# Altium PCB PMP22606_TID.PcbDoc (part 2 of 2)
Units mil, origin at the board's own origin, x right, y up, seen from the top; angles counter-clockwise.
Board outline 6300 x 4500 mil, 2 copper layers (Top Layer, Bottom Layer), stack 62 mil thick; 94 components, 37 nets, 207 pads, 120 vias.
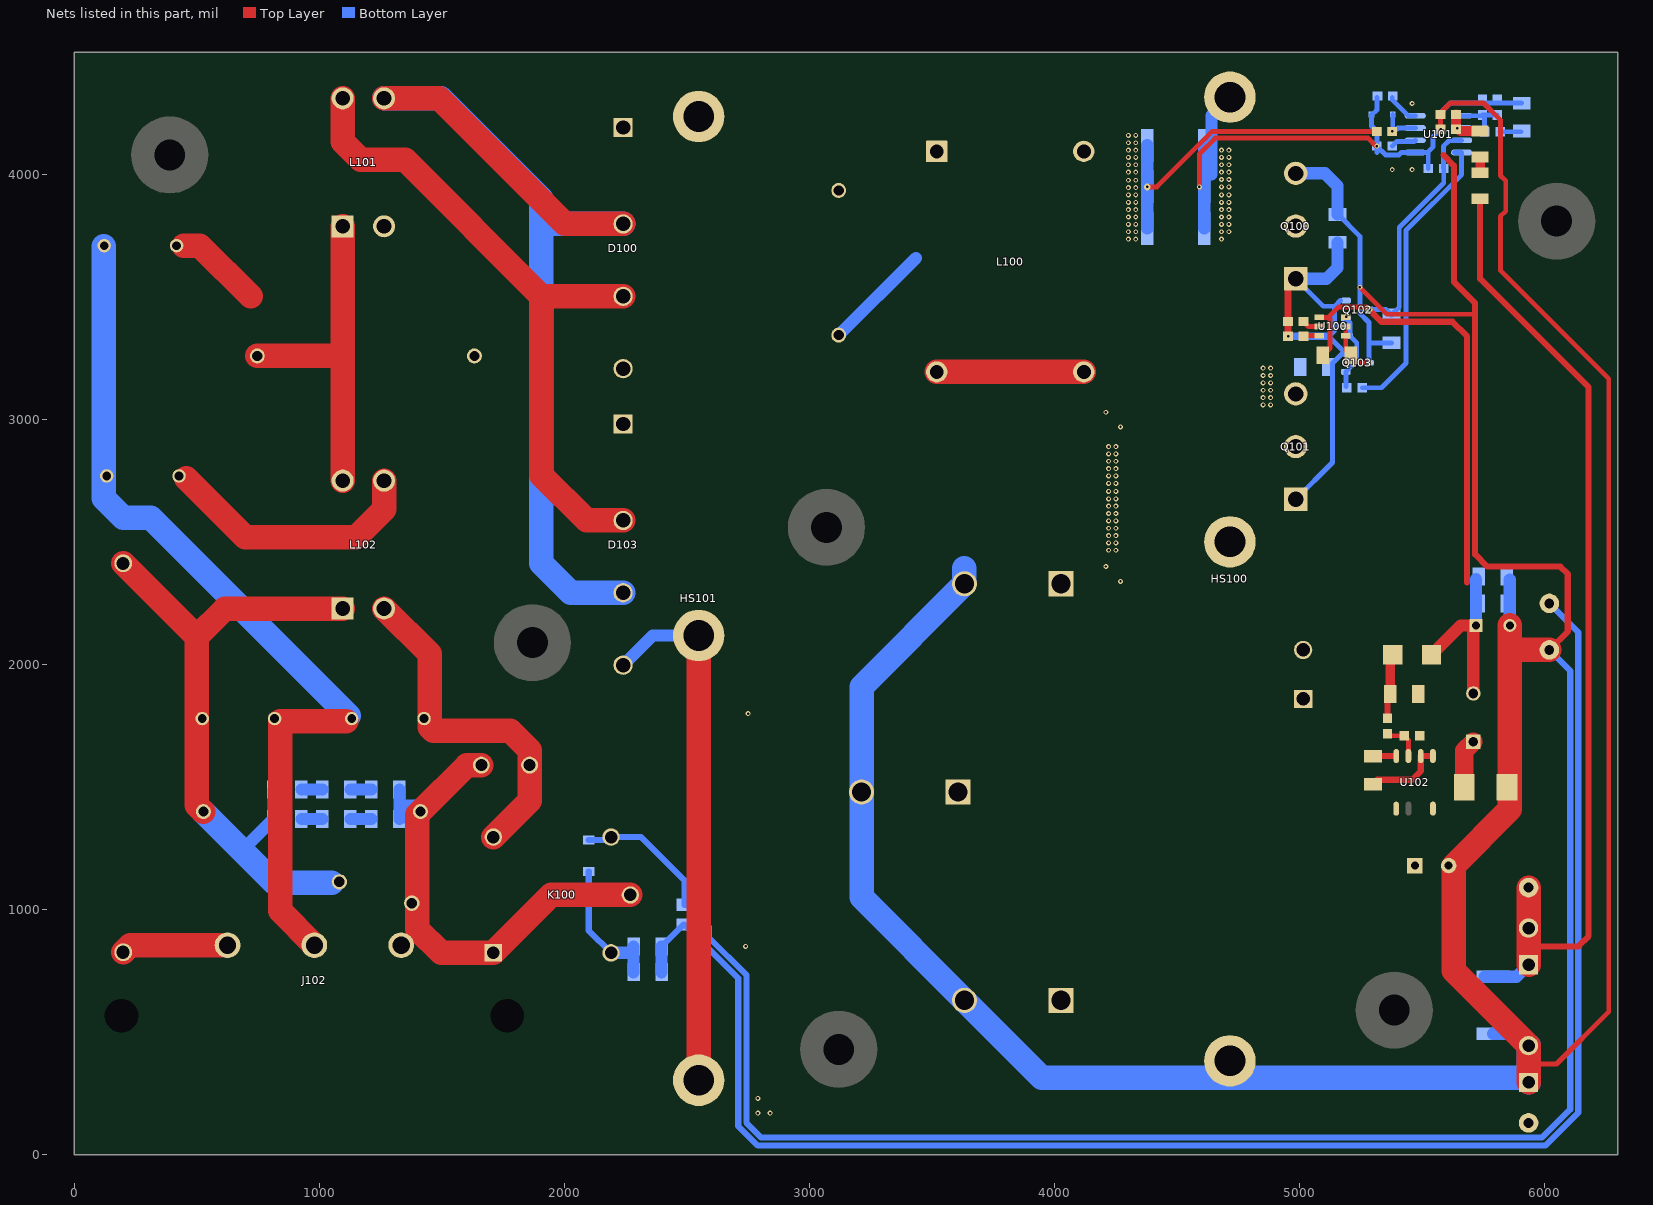
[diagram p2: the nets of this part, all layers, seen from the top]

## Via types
v1: diameter 20, hole 10, Top Layer to Bottom Layer, 112 vias
v2: diameter 28, hole 10, Top Layer to Bottom Layer, 8 vias

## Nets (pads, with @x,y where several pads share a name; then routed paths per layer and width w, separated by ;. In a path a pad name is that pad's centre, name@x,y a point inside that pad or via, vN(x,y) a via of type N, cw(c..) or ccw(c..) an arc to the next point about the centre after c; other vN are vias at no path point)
15V: 15V.1 C110.1 C111.1 C112.1 C113.2 C123.1 D107.2 L103.2 Q102.3 R118.2 R120.2 R126.2 R127.2 U100.1 U101.7 | length 10284.2
  Top Layer w20: U100.1@5081.06,3417.4 5117.8,3417.4 ; C111.1@5095.79,3262.49 5125.2,3291.89 5125.2,3410 5117.8,3417.4 ; v2(5284.96,3449.06) 5274.02,3460 5160.39,3460 5117.8,3417.4
  Top Layer w25: v2(5284.96,3449.06) 5334.39,3399.63 5624.59,3399.63 5684.53,3339.68 5684.53,2336.5
  Top Layer w50: D107.2@5538.74,2040 5658.74,2160 C123.1@5721.1,2160 ; L103.2@5710,1882.43 C123.1@5710,2148.9
  Bottom Layer w20: Q102.3@5284.57,3449.06 5353.23,3449.06 C110.1@5375.2,3427.09 5407.32,3459.21 5407.32,3784.1 5589.02,3965.8 C112.1@5589.02,4024.88 ; C112.1@5587.52,4026.38 5587.52,4114.88 5612.52,4139.88 U101.7@5662.01,4139.88
  Bottom Layer w25: R120.2@2397.09,850 2487.09,940 C113.2@2490,940 2710,720 2710,117.13 2790,37.13 6003.62,37.13 6138.07,171.58 6138.07,2131.93 15V.1@6020,2250
  Bottom Layer w50: R118.2@2397.09,745.04 R120.2@2397.09,850 ; C123.1@5721.1,2160 R126.2@5721.1,2348.5
B+: C101.1 C102.1 C103.1 C122.1 D101.1 J100.1 J100.2 R100.2 R117.2 U102.5 U102.8 Vout.1 | length 4119.7
  Top Layer w25: R117.2@5737.52,3901.73 5737.52,3575 6180,3132.52 6180,891.93 6138.07,850 5935.2,850
  Top Layer w100: J100.1@5935.2,775 5935.2,850 J100.2@5935.2,925 Vout.1@5935.2,1090
  Bottom Layer w50: R100.2@5756.02,726.14 5886.34,726.14 J100.1@5935.2,775 J100.2@5935.2,925
GND: C101.2 C102.2 C103.2 C110.2 C111.2 C112.2 C113.1 C114.2 C115.2 C116.2 C117.2 C118.2 C119.2 C122.2 C123.2 D104.1 D106.2 D108.2 GND.1 HS100.1 HS100.2 HS100.3 J101.1 J101.2 K100.5 Q100.3 Q101.3 Q103.3 R100.1 R101.1 R102.1 R105.2 R106.2 R109.2 R122.1 R123.1 R126.1 R127.1 U100.4 U100.5 U101.1 | length 25603.5
  Top Layer w20: v1(4592.17,3950) 4592.17,4084.52 4656.11,4148.46 5280.23,4148.46 5312.69,4116 v1(5316.02,4116) ; U100.5@5189.33,3380 U100.4@5189.33,3342.6 5189.33,3283.12 C111.2@5209.96,3262.49 5240.28,3232.17 v2(5284.1,3232.17) ; v1(5247.01,3540) 5357.01,3430 5717.4,3430 ; v2(5576.02,4184.88) C118.2@5576.02,4244.88 ; C118.2@5576.02,4251.81 5616.18,4291.97 5751.26,4291.97 5820.02,4223.21 5820.02,3996.28 5841.97,3974.33 5841.97,3851.08 5820.02,3829.14 5820.02,3609.17 6262.5,3166.69 6262.5,583.13 6049.37,370 5935.2,370
  Top Layer w25: 5587.52,4080 5630.57,4036.95 5630.57,3561.74 5717.4,3474.91 5717.4,3430 5717.4,2450 5767.4,2400 6065,2400 6095,2370 6095,2135 GND.1@6020,2060
  Top Layer w100: C123.2@5858.9,2160 5858.9,1408.9 5630,1180 5630,750.2 J101.2@5935.2,445 5935.2,370 J101.1@5935.2,295 ; 5878.9,2060 GND.1@6020,2060
  Bottom Layer w20: R101.1@5158.11,3837.09 5247.01,3748.19 v1(5247.01,3540) 5247.01,3433.3 5284.1,3396.21 v2(5284.1,3232.17) ; D106.2@5294.21,4244.88 5294.21,4198.15 C114.2@5316.02,4176.34 C115.2@5316.02,4116.34 v1(5316.02,4116) C115.2@5316.02,4115.67 ; 5298.11,3312.91 C110.2@5375.2,3312.91 ; 5307.52,4254.88 5316.02,4263.39 R122.1@5316.02,4314.88 ; 5316.02,4089.38 C115.2@5316.02,4115.67 ; C112.2@5526.02,4024.88 5526.02,4093.39 ; C119.2@5907.52,4291.97 5616.18,4291.97 5576.02,4251.81 v2(5576.02,4184.88) 5546.02,4154.88 5546.02,4113.39 5526.02,4093.39 ; C115.2@5316.02,4115.67 5351.93,4079.76 5406.1,4079.76 5416.22,4089.88 U101.1@5473.03,4089.88 5522.52,4089.88 5526.02,4093.39
  Bottom Layer w25: D104.1@2100,1284.47 K100.5@2179.04,1284.47 ; K100.5@2190.79,1296.22 2313.78,1296.22 2490,1120 C113.1@2490,1020 2500,1020 2590,930 2590,886.49 2742.87,733.62 2742.87,130.74 2803.62,70 5990,70 6105.2,185.2 6105.2,1974.8 GND.1@6020,2060
  Bottom Layer w50: R109.2@4611.34,3780 R106.2@4611.34,3950 R105.2@4611.34,4120 ; 4641.34,4000 4641.34,4240.91 HS100.1@4716.54,4316.1 ; Q100.3@4985.2,4005 5104.2,4005 5155.2,3954.01 R101.1@5155.2,3837.09 ; R100.1@5790,493.86 5886.34,493.86 J101.2@5935.2,445 ; C123.2@5858.9,2160 R126.1@5858.9,2347.87
  Bottom Layer w100: 3633.15,2392.95 C101.2@3633.15,2330 3213.15,1910 C102.2@3213.15,1480 3213.15,1050 C103.2@3633.15,630 3948.43,314.72 J101.1@5915.47,314.72 ; J101.1@5935.2,295 J101.2@5935.2,445
  other v1: 2790,170 2840,170 2790,230 2740,850 2750,1800 4270,2340 4210,2400.62 4221.34,2466.77 4251.34,2466.77 4221.34,2496.77 4251.34,2496.77 4221.34,2526.77 4251.34,2526.77 4221.34,2556.77 4251.34,2556.77 4221.34,2586.77 4251.34,2586.77 4221.34,2616.77 4251.34,2616.77 4221.34,2646.77 4251.34,2646.77 4221.34,2676.77 4251.34,2676.77 4221.34,2706.77 4251.34,2706.77 4221.34,2740 4251.34,2740 4221.34,2770 4251.34,2770 4221.34,2800 4251.34,2800 4221.34,2830 4251.34,2830 4221.34,2860 4251.34,2860 4221.34,2890 4251.34,2890 4270,2970 4210,3030 4852.2,3060 4882.2,3060 4852.2,3090 4882.2,3090 4852.2,3120 4882.2,3120 4852.2,3150 4882.2,3150 4852.2,3180 4882.2,3180 4852.2,3210 4882.2,3210 4682.2,3736.77 4682.2,3766.77 4712.2,3766.77 4682.2,3796.77 4712.2,3796.77 4682.2,3826.77 4712.2,3826.77 4682.2,3856.77 4712.2,3856.77 4682.2,3886.77 4712.2,3886.77 4682.2,3916.77 4712.2,3916.77 4682.2,3950 4712.2,3950 4682.2,3980 4712.2,3980 4682.2,4010 4712.2,4010 5379.02,4020 5460,4020 4682.2,4040 4712.2,4040 4682.2,4070 4712.2,4070 4682.2,4100 4712.2,4100 5460,4290
NetC100_1: C100.1 D100.1 D103.1 L100.1 L100.2
NetC100_2: C100.2 D100.4 D103.4 HS101.1 HS101.2 HS101.3 R105.1 R106.1 R109.1 R115.2 | length 3990.3
  Top Layer w20: v2(4379.06,3950) 4418.23,3950 4618.23,4150 4644.57,4176.34 R115.2@5316.02,4176.34
  Top Layer w100: HS101.1@2548.66,303.9 HS101.2@2548.66,2118.86
  Bottom Layer w50: D103.4@2240,1997.87 2360.98,2118.86 HS101.2@2548.66,2118.86 ; C100.2@3120,3344.72 3435.28,3660 ; R109.1@4379.06,3780 v2(4379.06,3950) R105.1@4379.06,4120
  other v1: 4302.2,3736.77 4332.2,3736.77 4302.2,3766.77 4332.2,3766.77 4302.2,3796.77 4332.2,3796.77 4302.2,3826.77 4332.2,3826.77 4302.2,3856.77 4332.2,3856.77 4302.2,3886.77 4332.2,3886.77 4302.2,3916.77 4332.2,3916.77 4302.2,3946.77 4332.2,3946.77 4302.2,3976.77 4332.2,3976.77 4302.2,4010 4332.2,4010 4302.2,4040 4332.2,4040 4302.2,4070 4332.2,4070 4302.2,4100 4332.2,4100 4302.2,4130 4332.2,4130 4302.2,4160 4332.2,4160
NetC104_1: C104.1 C106.1 F100.2 L102.1 R103.2 R104.2 RV100.2 | length 2720.5
  Top Layer w100: F100.2@200,2413.7 500,2113.7 ; C106.1@527.09,1400 500,1427.09 500,2113.7 ; L102.1@1095.5,2229 615.3,2229 500,2113.7
  Bottom Layer w50: 696.46,1253.54 R103.2@812.91,1370 R104.2@812.91,1490
  Bottom Layer w100: C106.1@527.09,1400 817.09,1110 1050.31,1110
NetC105_1: C105.1 C107.1 L101.1 L102.4 | length 1735.3
  Top Layer w100: 446.81,3710 513.15,3710 720,3503.15 ; C107.1@747.09,3260 1085.5,3260 ; L102.4@1095.5,2751 L101.1@1095.5,3789
NetC106_2: C106.2 J102.2 K100.1 K100.3 R110.1 R111.1 R112.2 RV100.1 | length 1992.5
  Top Layer w100: R112.2@1661.57,1590 1602.91,1590 C106.2@1412.91,1400 1400,1387.09 1400,920.67 1496.89,823.78 K100.1@1710.47,823.78 1946.69,1060 K100.3@2269.53,1060
  Bottom Layer w50: R110.1@1327.09,1370 R111.1@1327.09,1490
  Bottom Layer w100: 1359.92,1400 C106.2@1412.91,1400
NetC107_2: C107.2 C109.2 L101.2 L102.3 | length 1070.7
  Top Layer w100: 457.17,2760 697.17,2520 1150,2520 1264.5,2634.5 L102.3@1264.5,2751
NetC108_2: C108.2 K100.2 L102.2 R112.1 | length 1424.6
  Top Layer w100: L102.2@1264.5,2229 1450,2043.5 1450,1744.99 1464.99,1730 1780,1730 1858.43,1651.57 R112.1@1858.43,1590 1858.43,1444.17 K100.2@1710.47,1296.22
NetC114_1: C114.1 D106.1 R115.1 U101.3 | length 166.4
  Bottom Layer w20: v2(5379.02,4176.34) 5388.98,4176.34 5402.52,4189.88 U101.3@5473.03,4189.88 ; C114.1@5380.83,4178.15 D106.1@5380.83,4244.88
NetC115_1: C115.1 U101.2 | length 103.8
  Bottom Layer w20: C115.1@5379.02,4116.34 5397.56,4134.88 5468.03,4134.88 U101.2@5473.03,4139.88
NetC116_1: C116.1 C117.1 R121.2 U101.5 | length 219
  Bottom Layer w20: U101.5@5662.01,4239.88 5744.02,4239.88 C117.1@5747.52,4243.39 ; R121.2@5756.02,4174.88 5756.02,4234.88 C117.1@5747.52,4243.39 ; C116.1@5807.52,4243.39 C117.1@5747.52,4243.39
NetC118_1: C118.1 R119.1 R123.2 U101.6 | length 155.4
  Top Layer w39.37: C118.1@5639.02,4244.88 5639.02,4195.08 v2(5644.21,4189.88) 5656.06,4178.03 R119.1@5737.52,4178.03
NetC119_1: C119.1 R121.1 | length 85.6
  Bottom Layer w20: R121.1@5819.02,4174.88 C119.1@5904.61,4174.88
NetC120_1: C120.1 D107.1 R124.2 | length 237.2
  Top Layer w25: R124.2@5360,1781.5 C120.1@5360,1868.58
  Top Layer w39.37: C120.1@5371.42,1880 D107.1@5371.42,2030.16
NetC120_2: C120.2 C121.2 D108.1 L103.1 R125.1 U102.1 U102.2 | length 529.4
  Top Layer w25: C121.2@5300,1512.47 5317.53,1530 5459.69,1530 5495,1565.32 U102.2@5495,1627.02 U102.1@5545,1627.02
  Top Layer w75: D108.1@5672.99,1500.05 5672.99,1648.57 L103.1@5710,1685.57
NetC121_1: C121.1 U102.4 | length 94.6
  Top Layer w25: C121.1@5300.38,1627.02 U102.4@5395,1627.02
NetD100_2: D100.2 D103.3 L101.3 | length 4195.2
  Top Layer w100: L101.3@1264.5,4311 1489,4311 2001.57,3798.43 D100.2@2240,3798.43
  Bottom Layer w100: L101.3@1264.5,4311 1496.4,4311 1906.85,3900.55 1906.85,2413.15 2026.85,2293.15 D103.3@2240,2293.15 ; 1915.28,3798.43 D100.2@2240,3798.43
NetD100_3: D100.3 D103.2 L101.4 | length 2722.2
  Top Layer w100: L101.4@1095.5,4311 1095.5,4134.5 1170,4060 1350,4060 1906.85,3503.15 ; D103.2@2240,2588.43 2091.57,2588.43 1906.85,2773.15 1906.85,3503.15 ; D100.3@2240,3503.15 1906.85,3503.15
NetD101_2: D101.2 L100.3 L100.4 Q100.2 Q101.2 | length 600
  Top Layer w100: L100.4@3520,3194.77 L100.3@4120,3194.77
NetD102_1: D102.1 Q100.1 Q101.1 Q102.2 Q103.2 R101.2 R102.2 R113.1 R114.2 | length 1820.1
  Top Layer w29.53: v2(4953.7,3340) R113.1@4953.7,3400 Q100.1@4953.7,3543.5
  Bottom Layer w20: Q101.1@4985.2,2675 5135.2,2825 5135.2,3230 5174.77,3269.57 Q103.2@5189.61,3269.57 5120.59,3338.59 D102.1@5120.59,3340.16 5143.9,3363.46 5143.9,3462.52 ; Q100.1@4985.2,3575 5097.68,3462.52 5143.9,3462.52 ; 5167.83,3486.46 5143.9,3462.52
  Bottom Layer w29.53: v2(4953.7,3340) D102.1@5120.43,3340
  Bottom Layer w50: Q100.1@4985.2,3575 5110.2,3575 5155.2,3620 R101.2@5155.2,3722.91
NetD102_2: D102.2 Q102.1 Q103.1 R116.1 U100.6 | length 314.1
  Bottom Layer w20: R116.1@5189.61,3134.09 Q103.1@5189.61,3194.77 5233.9,3239.06 5233.9,3313.46 D102.2@5207.2,3340.16 5207.2,3394.53 Q102.1@5190.08,3411.65
  other v2: 5191.65,3419.51
NetD104_2: D104.2 D105.2 | length 52.2
  Bottom Layer w25: D105.2@2100,1103.31 D104.2@2100,1155.53
NetD105_1: D105.1 K100.4 R118.1 R120.1 | length 442.1
  Bottom Layer w25: D105.1@2100,1016.69 2100,914.57 K100.4@2190.79,823.78 ; R120.1@2262.91,830 R120.1@2282.91,850
  Bottom Layer w50: K100.4@2190.79,823.78 R120.1@2269.13,823.78 ; R118.1@2282.91,745.04 R120.1@2282.91,850
NetF100_1: F100.1 J102.1 | length 437.6
  Top Layer w100: F100.1@200,826.3 228.7,855 J102.1@625.67,855
NetR103_1: R103.1 R107.2 | length 85.8
  Bottom Layer w50: R103.1@927.09,1370 R107.2@1012.91,1370
NetR104_1: R104.1 R108.2 | length 85.8
  Bottom Layer w50: R104.1@927.09,1490 R108.2@1012.91,1490
NetR107_1: R107.1 R110.2 | length 85.8
  Bottom Layer w50: R107.1@1127.09,1370 R110.2@1212.91,1370
NetR108_1: R108.1 R111.2 | length 85.8
  Bottom Layer w50: R108.1@1127.09,1490 R111.2@1212.91,1490
NetR113_2: R113.2 U100.2 | length 72.7
  Top Layer w20: R113.2@5016.69,3400 5036.69,3380 U100.2@5081.06,3380
NetR114_1: R114.1 U100.3 | length 61.8
  Top Layer w20: R114.1@5019.29,3342.6 U100.3@5081.06,3342.6
NetR116_2: R116.2 U101.8 | length 1203.2
  Bottom Layer w20: R116.2@5256.69,3130 5335.2,3130 5435.2,3230 5435.2,3772.56 5662.01,3999.37 U101.8@5662.01,4089.88 U101.8@5632.52,4089.88
NetR117_1: R117.1 R119.2 | length 63.7
  Top Layer w39.37: R117.1@5737.52,4008.03 R119.2@5737.52,4071.73
NetR122_2: R122.2 U101.4 | length 130.9
  Bottom Layer w20: R122.2@5379.02,4314.88 5379.02,4304.89 5444.02,4239.88 U101.4@5473.03,4239.88
NetR124_1: R124.1 R125.2 U102.3 | length 149.8
  Top Layer w20: R124.1@5368.5,1710 R125.2@5428.5,1710 5445,1693.5 U102.3@5445,1627.02
PE: C104.2 C105.2 C108.1 C109.1 J102.3 | length 3632.4
  Top Layer w100: 840,1762.83 840,995 J102.3@980,855 ; C104.2@840,1770 C108.1@1110,1770
  Bottom Layer w100: C105.2@120.65,3708.29 120.65,2679.35 200,2600 312.36,2600 C108.1@1120.65,1791.8
pads on no net: H101.1 H103.1 H105.1 H107.1 H109.1 H114.1 J102.MH1 J102.MH2 U102.6

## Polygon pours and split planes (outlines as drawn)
GND on Top Layer "GND" (solid, pour order 84): 5300,4066.28 5370,3996.28 5371.11,3997.39 5522.51,3997.39 5600,4074.88 5600,4280 5569,4311 5451,4311 5430,4290 5430,4174.88 5400,4144.88 5314.77,4144.88 5300,4130.11
NetF100_1 on Top Layer "F100_1" (solid, remove dead copper, pour order 40): 50,940 30,920 30,850 30,720 50,700 100,700 660,700 680,720 680,800 680,880 620,940
B+ on Top Layer "B+" (solid, pour order 42): 5440,1100 5350,1190 5350,1438.27 5361.73,1450 5400.02,1450 5410,1440.02 5410,1380 5420,1370 5490,1370 5510,1390 5510,1440.02 5519.98,1450 5568.27,1450 5580.08,1438.19 5580.08,1290.08 5510,1220 5510,1114.32 5495.68,1100
NetC120_2 on Top Layer "C120_2" (solid, pour order 44): 5250,1550 5240,1540 5240,1480 5250,1470 5341.73,1470 5371.79,1500.05 5579.95,1500.05 5630,1450 5700,1450 5710,1460 5710,1699.98 5519.98,1890 5485.77,1890 5475.75,1879.98 5475.75,1674.25 5481.65,1668.35 5481.65,1586.65 5445,1550
15V on Top Layer "15V" (solid, pour order 46): 5500,2181.73 5500,2010 5660,1850 5735.75,1850 5750,1864.25 5750,2200 5790,2240 5907.32,2240 5957.32,2190 6019.69,2190 6060,2230.31 6060,2312.36 6011.36,2361 5679.27,2361
NetC106_2 on Top Layer "C106_2" (solid, pour order 48): 1300,740 1270,770 1270,900 1341.37,971.37 1341.37,1509.4 1471.97,1640 1690,1640 1720,1610 1720,1500 1580,1360 1580,1140 1610,1110 2300,1110 2320.32,1089.68 2320.32,1000.32 2300,980 2010,980 1770,740
NetC108_2 on Top Layer "C108_2" (solid, pour order 50): 1230,2300 1220,2290 1220,2113.59 1400,1933.59 1400,1709.06 1429.06,1680 1430,1680 1450,1660 1700.74,1660 1740,1620.74 1740,1489.47 1600,1349.47 1600,1230 1620,1210 1890,1210 1980,1300 1980,1712.48 1392.48,2300
NetC107_2 on Top Layer "C107_2" (solid, pour order 52): 1230,3850 1307.8,3850 1331,3826.8 1331,3632.15 1661.57,3301.57 1661.57,2921.57 1430,2690 1230,2690 1212.91,2707.09 1212.91,3832.91
NetD100_2 on Top Layer "D100_2" (solid, pour order 58): 1220,4360 1220,4270 1230,4260 1430,4260 1960,3730 2280,3730 2300,3750 2300,3830 1695,4435 1295,4435
NetD100_3 on Top Layer "D100_3" (solid, pour order 60): 1140,4360 1110,4390 1055,4390 970,4305 970,4130 1164.72,3935.28 1329.45,3935.28 1427.64,3837.09 1427.64,3672.36 1760,3340 1760,2696.85 1976.85,2480 2250,2480 2290,2520 2290,2670 2070,2890 2070,3240 2290,3460 2290,3580 2280,3590 1970,3590 1385.12,4174.88 1195.12,4174.88 1140,4230
NetC105_1 on Top Layer "C105_1" (solid, pour order 62): 1140,3830 1120,3850 1050,3850 690,3490 690,3030 1030,2690 1120,2690 1140,2710
NetC104_1 on Top Layer "C104_1" (solid, pour order 64): 160,2460 130,2430 130,1650 430,1350 550.43,1350 580,1379.57 580,1596.64 550,1626.64 550,1910 680,2040 1020,2040 1140,2160 1140,2272.83 1092.83,2320 510,2320 370,2460
GND on Top Layer "GND" (solid, pour order 72): 5034.57,4070.42 4975,4130 4665.23,4130 4610,4074.77 4610,3931.77 4510,3831.77 4510,3380 4140,3010 3688.23,3010 3372.98,2694.75 3372.98,2481.32 2700,1808.34 2700,170 2860,10 5980,10 6030,60 6030,570 5850,750 5850,1121.1 6080,1351.1 6080,2080 6000,2160 5878.9,2160 5847.01,2128.11 5847.01,1414.94 5630,1197.94 5630,1080 5600,1050 5170,1050 4860,1360 4860,2960 4949.49,3049.49 5016.38,3049.49 5040,3073.11 5040,3180 4877.68,3342.32 4877.68,3877.68 4930,3930 4997.39,3930 5000,3927.39 5040,3967.39 5040,4065
NetC100_2 on Top Layer "C100_2" (solid, pour order 74): 2370,2200 2200,2030 2200,1960 2370,1790 2370,1220 2420,1170 2420,210 2460,170 2620,170 2660,210 2660,2470 3650,3460 4280,3460 4398.23,3578.23 4398.23,4401.77 4360,4440 2200,4440 2170,4410 2170,4120 2410,3880 2410,3439.21 2190,3219.21 2190,3170 2210,3150 2290,3150 2370,3070
15V on Bottom Layer "15V" (solid, pour order 86): 5410,3399.63 5400.37,3390 5320,3390 5270,3440 5270,3460 5280,3470 5404.49,3470 5410,3464.49
NetF100_1 on Bottom Layer "F100_1" (solid, remove dead copper, pour order 39): 50,940 30,920 30,850 30,720 50,700 100,700 660,700 680,720 680,800 680,880 620,940
NetD100_2 on Bottom Layer "D100_2" (solid, pour order 56): 2150,3730 2100,3680 2100,2439.76 2160,2379.76 2160.24,2380 2260,2380 2290,2350 2290,2230 2260,2200 2000,2200 1820,2380 1820,3870 1430,4260 1230,4260 1220,4270 1220,4360 1295,4435 1695,4435 2300,3830 2300,3750 2280,3730
B+ on Bottom Layer "B+" (solid, pour order 70): 3980,2400 3950,2370 3540,1960 3540,1000 3970,570 4100,570 4260,730 5960,730 6000,770 6000,1120 5980,1140 5920,1140 5870,1090 5563.74,1090 5363.74,1290 5260,1290 5110,1440 5110,1850 5050,1910 4570,1910 4079.38,2400.62
NetC100_1 on Bottom Layer "C100_1" (solid, pour order 66): 2200,4270 2178.98,4248.98 2178.98,4091.02 2387.52,3882.48 2387.52,3137.52 2310,3060 2210.79,3060 2190.79,3040 2190.79,2909.21 2230,2870 2660,2870 2840,3050 2840,3400 3335.94,3895.94 4055.94,3895.94 4162.35,4002.35 4162.35,4128.84 3951.19,4340 2948.89,4340 2698.78,4089.88 2480.12,4089.88 2300,4270
NetC100_2 on Bottom Layer "C100_2" (solid, pour order 76): 4210,3980 4210,4402.2 4247.8,4440 4350,4440 4470,4320 4470,3720 4450,3700 4200,3450 3647.09,3450 3350,3152.91 3350,2800 2480,1930 2235,1930 2200,1965 2200,2030 2370,2200 2370,2490 2910,3030 2910,3377.09 3382.91,3850 4080,3850
NetD101_2 on Bottom Layer "D101_2" (solid, pour order 68): 5040,3840 5020,3860 4910,3860 4300,3250 3484.28,3250 3466.45,3232.17 3467.4,3231.23 3467.4,3152.6 3482.48,3137.52 4222.48,3137.52 4350,3010 4350,2290 4640,2000 5039.84,2000 5070,2030.16 5070,2090 5030,2130 4750,2130 4510,2370 4510,2749.8 4580.2,2820 5010,2820 5040,2850 5040,2930 5010,2960 4828.2,2960 4770,3018.2 4770,3542.32 4957.68,3730 5020,3730 5040,3750
GND on Bottom Layer "GND" (solid, pour order 78): 4620,4440 4550.2,4370.2 4550.2,3733.03 4583.23,3700 4638.23,3700 4868.5,3930.28 5004.48,3930.28 5040,3965.8 5040,4400 5000,4440
GND on Bottom Layer "GND" (solid, pour order 80): 4510,3720 4540,3690 4668.89,3690 4690,3668.89 4510,3488.89 4510,3486.46 4510,3380 4140,3010 3688.23,3010 3372.98,2694.75 3372.98,2481.32 2700,1808.34 2700,855 2780,775 2780,160 2850,90 5970,90 6030,150 6030,570 5850,750 5850,1121.1 6080,1351.1 6080,2080 6000,2160 5878.9,2160 5847.01,2128.11 5847.01,1414.94 5630,1197.94 5630,1080 5600,1050 5170,1050 4860,1360 4860,2960 4949.49,3049.49 5016.38,3049.49 5040,3073.11 5040,3232.17 5012.17,3260 4867.37,3260 4867.37,3257.37 4820,3210 4820,3552.32 4877.68,3610 4877.68,3877.68 4930,3930 4997.39,3930 5000,3927.39 5070,3997.39 5070,4035 5034.57,4070.42 4748.65,4070.42 4510,3831.77
GND on Bottom Layer "GND" (solid, pour order 82): 5240,4440 5200,4400 5200,3970 5820,3350 5820,1950 5920,1850 5990,1850 6270,2130 6270,4400 6230,4440

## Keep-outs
Keep-Out Layer:
  text ".Layer_Name" at 577,-858.49 h60

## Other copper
Top Layer:
  text ".Layer_Name" at 577,-858.49 h60
Bottom Layer:
  text ".Layer_Name" at 577,-858.49 h60

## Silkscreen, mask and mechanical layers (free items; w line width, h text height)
Top Overlay:
  lines w7.01: 0,0 0,3543.31
  lines w10: 4985.2,3440 5005.2,3460 5115.2,3460 5135.2,3480 5145.2,3480 ; 5050,1610 5190,1750 5310,1750
  text ".PRJ_Number" at 2440,80 h60
  text "RevA" at 3040,80 h60
  text ".Layer_Name" at 577,-858.49 h60
Bottom Overlay:
  text ".Layer_Name" at 577,-858.49 h60
Top Paste:
  text ".Layer_Name" at 577,-858.49 h60
Bottom Paste:
  text ".Layer_Name" at 577,-858.49 h60
Top Solder:
  text ".Layer_Name" at 577,-858.49 h60
  text ".Layer_Name" at 577,-858.49 h60
Bottom Solder:
  text ".Layer_Name" at 577,-858.49 h60
Drill Guide:
  text ".Layer_Name" at 577,-858.49 h60
M1 Board Outline:
  the board outline again, w7
  text ".Layer_Name" at 577,-858.49 h60
M2 Board Dimensions:
  rectangle: 125,-400 500,-275
  rectangle: 0,-275 125,-150
  lines w7: 0,-275 1000,-275 ; 125,-400 125,-150 ; 250,-400 250,-150 ; 500,-400 500,-150 ; 750,-400 750,-150 ; 0,-400 0,-150 1000,-150 1000,-400 0,-400
  text ".Layer_Name" at 577,-858.49 h60
M3 3D STEP Top:
  text ".Layer_Name" at 577,-858.49 h60
M4 3D STEP Bottom:
  text ".Layer_Name" at 577,-858.49 h60
M5 Assembly Top:
  lines w10: -292,-930.17 6308,-930.17 ; -292,-726.83 6310,-726.83 ; -292,-523.5 -292,-1133.5 3713,-1133.5 6310,-1133.5 6310,-523.5 -291.5,-523.5 -291.5,-1133.5 1284,-1133.5 ; 2173,-1133.5 2173,-523.5 ; 3440,-726.83 3440,-523.5 ; 4280,-726.83 4280,-523.5 ; 4902,-1140 4902,-937.17
  text "COMPONENTS MARKED 'DNP' SHOULD NOT BE POPULATED." at 1153.5,-318.5 h60
  text "ASSEMBLY VARIANT:" at 1153,-434 h60
  text ".VariantName" at 2189,-434 h60
  text "PCB VIEWED FROM TOP SIDE" at -228.5,-655.67 h60
  text "BOARD #:" at 2248,-655.67 h60
  text ".PRJ_Number" at 2793.5,-655.67 h60
  text "REV:" at 3638,-655.67 h60
  text ".PCB_Rev" at 3929.5,-655.67 h60
  text "SVN REV:" at 4476,-655.67 h60
  text ".VersionControl_RevNumber" at 4982,-655.67 h60
  text "PLOT NAME =" at -228.5,-1064.34 h60
  text ".plot_File_Name" at 577,-1064.34 h60
  text "GENERATED    :" at 2250,-1064.34 h60
  text ".Print_Date" at 3119.5,-1064.34 h60
  text ".Print_Time" at 3848.5,-1064.34 h60
  text "TEXAS INSTRUMENTS" at 5113,-1064.34 h60
M6 Assembly Bottom:
  lines w10: -292.5,-727.33 6309.5,-727.33 ; -290.5,-930.67 6309.5,-930.67 ; 1115.5,-1140.5 1115.5,-937.67 ; 1737.5,-727.33 1737.5,-524 ; 2577.5,-727.33 2577.5,-524 ; 3844.5,-1134 3844.5,-524 ; 4733.5,-1134 6309,-1134 6309,-524 -292.5,-524 -292.5,-1134 2304.5,-1134 6309.5,-1134 6309.5,-524
  text "COMPONENTS MARKED 'DNP' SHOULD NOT BE POPULATED." at 6102,-318 h60
  text ".VariantName" at 5058,-434 h60
  text "ASSEMBLY VARIANT:" at 6097,-434 h60
  text ".VersionControl_RevNumber" at 1035.5,-656.17 h60
  text "SVN REV:" at 1541.5,-656.17 h60
  text ".PCB_Rev" at 2088,-656.17 h60
  text "REV:" at 2379.5,-656.17 h60
  text ".PRJ_Number" at 3224,-656.17 h60
  text "BOARD #:" at 3769.5,-656.17 h60
  text "PCB VIEWED FROM BOTTOM SIDE" at 6246,-656.17 h60
  text "TEXAS INSTRUMENTS" at 904.5,-1064.84 h60
  text ".Print_Time" at 2169,-1064.84 h60
  text ".Print_Date" at 2898,-1064.84 h60
  text "GENERATED    :" at 3767.5,-1064.84 h60
  text ".plot_File_Name" at 5440.5,-1064.84 h60
  text "PLOT NAME =" at 6246,-1064.84 h60
M9 Title Sheet:
  drawing of 57 lines, arcs and shapes, not listed
  text "1" at 739.84,8036.5 h70
  text "2" at 3235.5,8036.5 h70
  text "3" at 5724.84,8036.5 h70
  text "4" at 8231.51,8036.5 h70
  text "5" at 10730.5,8036.5 h70
  text "6" at 13235.5,8036.5 h70
  text "A" at -416.5,6893.5 h70
  text "A" at 14383.5,6893.5 h70
  text "B" at -416.5,4513.5 h70
  text "B" at 14383.5,4513.5 h70
  text "C" at -416.5,2138.5 h70
  text "C" at 14383.5,2138.5 h70
  text "PROJECT TITLE:" at 11343.5,277.5 h45
  text ".PRJ_Title" at 11393.5,144.17 h70
  text "DESIGNED FOR:" at 11343.5,-23.5 h45
  text ".PRJ_Customer" at 11393.5,-163.5 h70
  text "D" at -416.5,-231.5 h70
  text "D" at 14383.5,-231.5 h70
  text "FILE NAME:" at 11343.5,-323.5 h45
  text ".PCB_File_Name_No_Path" at 11393.5,-443.5 h70
  text "Texas Instruments (TI) and/or its licensors do not warrant the accuracy or completeness of this specification" at 6374,-605.34 h45
  text "ENGINEER:" at 11343.5,-613.5 h45
  text "LAYOUT BY:" at 12848.5,-613.5 h45
  text "or any information contained therein. TI and/or its licensors do not warrant that this design will meet" at 6329.01,-718 h45
  text ".PRJ_Engineer" at 11393.5,-768.49 h70
  text ".PCB_Layout" at 12899,-768.49 h70
  text "the specifications, will be suitable for your application or fit for any particular purpose, or will operate in" at 6329.01,-830.67 h45
  text ".Layer_Name" at 577,-858.49 h60
  text "ALTIUM DESIGNER VERSION:" at 12848.5,-923.5 h45
  text "an implementation. TI and/or its licensors do not warrant that the design is production worthy. You should" at 6329.01,-943.33 h45
  text "completely validate and test your design implementation to confirm the system functionality for your application." at 6374,-1056 h45
  text ".print_Scale" at 11393.5,-1056.83 h70
  text ".Application_BuildNumber" at 12899,-1056.83 h70
  text "1" at 739.84,-1263.5 h70
  text "2" at 3235.5,-1263.5 h70
  text "3" at 5724.84,-1263.5 h70
  text "4" at 8231.51,-1263.5 h70
  text "5" at 10730.5,-1263.5 h70
  text "6" at 13235.5,-1263.5 h70
M10 Fab Notes:
  drawing of 185 lines, arcs and shapes, not listed
  text "DESIGN INFORMATION" at 12381.02,5910 h60
  text "MIN. TRACK WIDTH:" at 11736.46,5730 h60
  text "10" at 12832.7,5730 h60
  text "MIL" at 12987.46,5730 h60
  text "MIN. CLEARANCE:" at 11736.46,5598 h60
  text "0.2" at 12772.7,5598 h60
  text "mm" at 12987.46,5598 h60
  text "MIN. VIA PAD SIZE:" at 11736.46,5466 h60
  text "10" at 12802.71,5466 h60
  text "MIL" at 12987.46,5466 h60
  text "0.05mm (2MIL)" at 12431.46,5324.29 h60
  text "MINIMUM ANNULAR RING" at 11407.23,5320 h60
  text "EXTERNAL" at 13139.46,5320 h60
  text "PER" at 11607.23,5202 h60
  text "IPC-D-275 CLASS 2 LEVEL C" at 11827.23,5202 h60
  text "MIL, HOLES" at 13315.46,5089.71 h60
  text "+/-" at 12923,5089 h60
  text "+/-" at 13777,5089 h60
  text "REGISTRATION TOLERANCES:" at 11407.23,5084 h60
  text "METAL" at 12607,5084 h60
  text "5" at 13183.2,5084 h60
  text "3" at 14016.2,5084 h60
  text "MIL" at 14132.46,5084 h60
  text "MATERIAL:" at 11332.46,4874.54 h60
  text "FR-4 High Tg" at 12318.9,4734.21 h60
  text "FR-408" at 11753.46,4725.64 h60
  text "X" at 12165.46,4725.64 h60
  text "OTHER" at 13241.46,4725.64 h60
  text "62 MIL (1.6mm) +/-10%" at 12073.56,4562.92 h60
  text "THICKNESS:" at 11407.23,4558.64 h60
  text "X" at 11945.4,4558.64 h60
  text "OTHER" at 13358.46,4558.64 h60
  text "TOLERANCE:" at 11407.23,4400.64 h60
  text "X" at 12246.53,4400.64 h60
  text "ANSI IPC-6012 TYPE 3 CLASS 2" at 12433.48,4400.64 h60
  text "OTHER +/-" at 12433.46,4244.64 h60
  text "BOW & TWIST:" at 11407.23,4087.64 h60
  text "X" at 12246.53,4087.64 h60
  text "ANSI IPC-6012 TYPE 3 CLASS 2" at 12433.48,4087.64 h60
  text "OTHER +/-" at 12433.46,3929.13 h60
  text "DRILLING:" at 11332.46,3790.64 h60
  text "REFERENCE:" at 11407.23,3673.64 h60
  text "X" at 12055.46,3673.64 h60
  text "AS SHOWN" at 12242.46,3673.64 h60
  text "X" at 12956.46,3673.64 h60
  text "NC_DRILL FILES" at 13093.46,3673.64 h60
  text "PTH MIN COPPER THICKNESS:" at 11407.23,3515.64 h60
  text "X" at 12757.46,3515.64 h60
  text "1MIL" at 12894.46,3515.64 h60
  text "OTHER" at 13391.46,3515.64 h60
  text "BOARD FINISH:" at 11332.46,3356.64 h60
  text "SILKSCREEN:" at 11487.68,3238.64 h60
  text "X" at 12436.46,3238.64 h60
  text "TOP" at 12562.46,3238.64 h60
  text "X" at 12946.46,3238.64 h60
  text "BOTTOM" at 13073.46,3238.64 h60
  text "SILKSCREEN COLOR:" at 11487.68,3071.64 h60
  text "X" at 12435.42,3071.64 h60
  text "WHITE" at 12562.46,3071.64 h60
  text "OTHER" at 13073.46,3071.64 h60
  text "SOLDER RESIST COLOR:" at 11487.68,2901.64 h60
  text "X" at 12055.42,2742.44 h60
  text "GREEN" at 12182.46,2742.44 h60
  text "BLUE" at 12773.46,2742.44 h60
  text "OTHER" at 13311.46,2742.44 h60
  text "IMMERSION GOLD (ENIG)" at 12393.46,2553.92 h60
  text "ENEPIG" at 13731,2550.64 h60
  text "SURFACE FINISH:" at 11332.46,2549.64 h60
  text "IMM. TIN/SILVER OR EQUIV" at 11662,2392.64 h60
  text "OTHER" at 13093.46,2392.64 h60
  text "X" at 11500,2390 h60
  text "ARRAY/PANEL:" at 11332.46,2213.64 h60
  text "CUT AND TRIM PER MECH LAYER 1" at 12393.46,2209.35 h60
  text "N.C. ROUTE" at 12393.46,2057.64 h60
  text "X" at 13072.46,2057.64 h60
  text "V. SCORE" at 13259.46,2057.64 h60
  text "CERTIFICATION:" at 11332.46,1920.64 h60
  text "MATERIALS AND WORKMANSHIP FOR ALL PCBS" at 12057.46,1920.64 h60
  text "TO MEET OR EXCEED THE REQUIREMENTS OF:" at 12057.46,1822.64 h60
  text "X" at 11683.96,1686.13 h60
  text "ANSI IPC-A-600F CLASS ->" at 11822.96,1686.13 h60
  text "X" at 13462.02,1686.13 h60
  text "2" at 13580.96,1686.14 h60
  text "1" at 13265.96,1684.64 h60
  text "3" at 13934.96,1684.64 h60
  text "X" at 11686.02,1526.64 h60
  text "UL 94V-0" at 11822.96,1526.64 h60
  text "X" at 12498.02,1526.64 h60
  text "RoHS" at 12634.96,1526.64 h60
  text "OTHER" at 13279.36,1526.64 h60
  text "PER ORDER" at 13676.42,1526.64 h60
  text "ADDITIONAL REQUIREMENTS:" at 11332.46,1385.64 h60
  text "MICROSECTION:" at 11407.23,1270.64 h60
  text "YES" at 12312.96,1270.64 h60
  text "REQUIRED" at 13174.46,1114.49 h60
  text "BARE BOARD ELEC. TEST:" at 11407.23,1111.64 h60
  text "NONE" at 12712.96,1111.64 h60
  text "PER ORDER" at 13766.46,1111.64 h60
  text "X" at 12590,1110 h60
  text "MANUFACTURER'S UL:" at 11407.23,954.64 h60
  text "RAIL" at 12572.96,950.35 h60
  text "METAL" at 13064.77,950.35 h60
  text "X" at 13440,950 h60
  text "SILK" at 13576.46,950.35 h60
  text ".Layer_Name" at 577,-858.49 h60
M11 Gerber Information:
  lines w10: -292,-930.17 6308,-930.17 ; -292,-726.83 6310,-726.83 ; -292,-523.5 -292,-1133.5 3713,-1133.5 6310,-1133.5 6310,-523.5 -291.5,-523.5 -291.5,-1133.5 1284,-1133.5 ; 2173,-1133.5 2173,-523.5 ; 3440,-726.83 3440,-523.5 ; 4280,-726.83 4280,-523.5 ; 4902,-1140 4902,-937.17
  text "ALL ARTWORK VIEWED FROM TOP SIDE" at -228.5,-655.67 h60
  text "BOARD #:" at 2248,-655.67 h60
  text ".PRJ_Number" at 2793.5,-655.67 h60
  text "REV:" at 3638,-655.67 h60
  text ".PCB_Rev" at 3929.5,-655.67 h60
  text "SVN REV:" at 4476,-655.67 h60
  text ".VersionControl_RevNumber" at 4982,-655.67 h60
  text "LAYER NAME =" at -228.5,-858.49 h60
  text "PLOT NAME =" at -228.5,-1064.34 h60
  text ".plot_File_Name" at 577,-1064.34 h60
  text "GENERATED    :" at 2250,-1064.34 h60
  text ".Print_Date" at 3119.5,-1064.34 h60
  text ".Print_Time" at 3848.5,-1064.34 h60
  text "TEXAS INSTRUMENTS" at 5113,-1064.34 h60
M12 Stackup:
  drawing of 191 lines, arcs and shapes, not listed
  text "Layer" at 57.5,5537.5 h60
  text "Name" at 467.41,5537.5 h60
  text "Material" at 1397.16,5537.5 h60
  text "Thickness" at 2256.92,5537.5 h60
  text "Constant" at 2906.76,5537.5 h60
  text "Board Layer Stack" at 3476.62,5537.5 h60
  text "1" at 57.5,5417.5 h60
  text "Top Overlay" at 467.41,5417.5 h60
  text "2" at 57.5,5297.5 h60
  text "Top Solder" at 467.41,5297.5 h60
  text "Solder Resist" at 1397.16,5297.5 h60
  text "0.40mil" at 2256.92,5297.5 h60
  text "3.5" at 2906.76,5297.5 h60
  text "3" at 57.5,5177.5 h60
  text "Top Layer" at 467.41,5177.5 h60
  text "Copper" at 1397.16,5177.5 h60
  text "1.40mil" at 2256.92,5177.5 h60
  text "4" at 57.5,5057.5 h60
  text "Dielectric1" at 467.41,5057.5 h60
  text "FR-4" at 1397.16,5057.5 h60
  text "59.20mil" at 2256.92,5057.5 h60
  text "4.8" at 2906.76,5057.5 h60
  text "5" at 57.5,4937.5 h60
  text "Bottom Layer" at 467.41,4937.5 h60
  text "Copper" at 1397.16,4937.5 h60
  text "1.40mil" at 2256.92,4937.5 h60
  text "6" at 57.5,4817.5 h60
  text "Bottom Solder" at 467.41,4817.5 h60
  text "Solder Resist" at 1397.16,4817.5 h60
  text "0.40mil" at 2256.92,4817.5 h60
  text "3.5" at 2906.76,4817.5 h60
  text "7" at 57.5,4697.5 h60
  text "Bottom Overlay" at 467.41,4697.5 h60
  text ".Layer_Name" at 577,-858.49 h60
M13 Component Bodies Top:
  text ".Layer_Name" at 577,-858.49 h60
M14 Component Bodies Bottom:
  text ".Layer_Name" at 577,-858.49 h60
M15 Courtyards Top:
  text ".Layer_Name" at 577,-858.49 h60
M16 Courtyards Bottom:
  text ".Layer_Name" at 577,-858.49 h60
Drill Drawing:
  lines w10: -32.71,4952.5 -32.71,4969.17 -16.04,4985.83 -32.71,5002.5 -32.71,5019.17 -16.04,5019.17 0.62,5002.5 17.29,5019.17 33.96,5019.17 33.96,5002.5 17.29,4985.83 33.96,4969.17 33.96,4952.5 17.29,4952.5 0.62,4969.17 -16.04,4952.5 -32.71,4952.5 ; -32.71,5402.5 33.96,5402.5 33.96,5469.17 -32.71,5469.17 -32.71,5402.5 ; -32.71,6219.17 33.96,6219.17 0.62,6152.5 -32.71,6219.17 ; -32.71,7369.17 -16.04,7369.17 -16.04,7352.5 17.29,7352.5 17.29,7369.17 33.96,7369.17 33.96,7402.5 17.29,7402.5 17.29,7419.17 -16.04,7419.17 -16.04,7402.5 -32.71,7402.5 -32.71,7369.17 ; -32.71,7502.5 0.62,7519.17 33.96,7502.5 17.29,7535.83 33.96,7569.17 0.62,7552.5 -32.71,7569.17 -16.04,7535.83 -32.71,7502.5 ; -32.71,7669.17 -16.04,7669.17 0.62,7652.5 17.29,7669.17 33.96,7669.17 17.29,7685.83 33.96,7702.5 17.29,7702.5 0.62,7719.17 -16.04,7702.5 -32.71,7702.5 -16.04,7685.83 -32.71,7669.17
  lines w15: -92.5,4607.5 10488.57,4607.5 ; -92.5,7757.5 10488.57,7757.5 ; 458.38,4457.5 458.38,7907.5 ; 1048.22,4457.5 1048.22,7907.5 ; 2197.88,4457.5 2197.88,7907.5 ; 2703.76,4457.5 2703.76,7907.5 ; 3437.56,4457.5 3437.56,7907.5 ; 4937.11,4457.5 4937.11,7907.5 ; 5526.96,4457.5 5526.96,7907.5 ; 6272.76,4457.5 6272.76,7907.5 ; 6922.59,4457.5 6922.59,7907.5 ; 7776.35,4457.5 7776.35,7907.5 ; 9109.96,4457.5 9109.96,7907.5 ; -92.5,4457.5 10488.57,4457.5 10488.57,7907.5 -92.5,7907.5 -92.5,4457.5
  text "Symbol" at -2.5,7802.5 h72
  text "Count" at 503.38,7802.5 h72
  text "Hole Size" at 1093.22,7802.5 h72
  text "Plated" at 2242.88,7802.5 h72
  text "Hole Type" at 2748.76,7802.5 h72
  text "Drill Layer Pair" at 3482.56,7802.5 h72
  text "Via/Pad" at 4982.11,7802.5 h72
  text "Pad Shape" at 5571.96,7802.5 h72
  text "Template" at 6317.76,7802.5 h72
  text "Description" at 6967.59,7802.5 h72
  text "Hole Tolerance (+)" at 7821.35,7802.5 h72
  text "Hole Tolerance (-)" at 9154.96,7802.5 h72
  text "2" at 503.38,7652.5 h60
  text "33.00mil (0.838mm)" at 1093.22,7652.5 h60
  text "PTH" at 2242.88,7652.5 h60
  text "Round" at 2748.76,7652.5 h60
  text "Top Layer - Bottom Layer" at 3482.56,7652.5 h60
  text "Pad" at 4982.11,7652.5 h60
  text "(Mixed)" at 5571.96,7652.5 h60
  text "(Mixed)" at 6317.76,7652.5 h60
  text "2" at 503.38,7502.5 h60
  text "33.47mil (0.850mm)" at 1093.22,7502.5 h60
  text "PTH" at 2242.88,7502.5 h60
  text "Round" at 2748.76,7502.5 h60
  text "Top Layer - Bottom Layer" at 3482.56,7502.5 h60
  text "Pad" at 4982.11,7502.5 h60
  text "(Mixed)" at 5571.96,7502.5 h60
  text "(Mixed)" at 6317.76,7502.5 h60
  text "2" at 503.38,7352.5 h60
  text "39.37mil (1.000mm)" at 1093.22,7352.5 h60
  text "PTH" at 2242.88,7352.5 h60
  text "Round" at 2748.76,7352.5 h60
  text "Top Layer - Bottom Layer" at 3482.56,7352.5 h60
  text "Pad" at 4982.11,7352.5 h60
  text "(Mixed)" at 5571.96,7352.5 h60
  text "(Mixed)" at 6317.76,7352.5 h60
  text "2" at 503.38,7202.5 h60
  text "43.31mil (1.100mm)" at 1093.22,7202.5 h60
  text "PTH" at 2242.88,7202.5 h60
  text "Round" at 2748.76,7202.5 h60
  text "Top Layer - Bottom Layer" at 3482.56,7202.5 h60
  text "Pad" at 4982.11,7202.5 h60
  text "Rounded" at 5571.96,7202.5 h60
  text "c160h110" at 6317.76,7202.5 h60
  text "X" at -31.59,7192.51 h66.67
  text "_" at -31.59,7075.83 h66.67
  text "2" at 503.38,7052.5 h60
  text "49.21mil (1.250mm)" at 1093.22,7052.5 h60
  text "PTH" at 2242.88,7052.5 h60
  text "Round" at 2748.76,7052.5 h60
  text "Top Layer - Bottom Layer" at 3482.56,7052.5 h60
  text "Pad" at 4982.11,7052.5 h60
  text "Rounded" at 5571.96,7052.5 h60
  text "c175h125" at 6317.76,7052.5 h60
  text "2" at 503.38,6902.5 h60
  text "53.15mil (1.350mm)" at 1093.22,6902.5 h60
  text "PTH" at 2242.88,6902.5 h60
  text "Round" at 2748.76,6902.5 h60
  text "Top Layer - Bottom Layer" at 3482.56,6902.5 h60
  text "Pad" at 4982.11,6902.5 h60
  text "Rounded" at 5571.96,6902.5 h60
  text "c185h135" at 6317.76,6902.5 h60
  text "]" at -20.48,6892.51 h66.67
  text "^" at -31.59,6764.73 h66.67
  text "2" at 503.38,6752.5 h60
  text "55.12mil (1.400mm)" at 1093.22,6752.5 h60
  text "PTH" at 2242.88,6752.5 h60
  text "Round" at 2748.76,6752.5 h60
  text "Top Layer - Bottom Layer" at 3482.56,6752.5 h60
  text "Pad" at 4982.11,6752.5 h60
  text "(Mixed)" at 5571.96,6752.5 h60
  text "(Mixed)" at 6317.76,6752.5 h60
  text "2" at 503.38,6602.5 h60
  text "137.80mil (3.500mm)" at 1093.22,6602.5 h60
  text "NPTH" at 2242.88,6602.5 h60
  text "Round" at 2748.76,6602.5 h60
  text "Top Layer - Bottom Layer" at 3482.56,6602.5 h60
  text "Pad" at 4982.11,6602.5 h60
  text "Rounded" at 5571.96,6602.5 h60
  text "c100hn350" at 6317.76,6602.5 h60
  text "W" at -31.59,6592.51 h66.67
  text "3" at 503.38,6452.5 h60
  text "70.00mil (1.778mm)" at 1093.22,6452.5 h60
  text "PTH" at 2242.88,6452.5 h60
  text "Round" at 2748.76,6452.5 h60
  text "Top Layer - Bottom Layer" at 3482.56,6452.5 h60
  text "Pad" at 4982.11,6452.5 h60
  text "Rounded" at 5571.96,6452.5 h60
  text "c267h178" at 6317.76,6452.5 h60
  text "V" at -31.59,6442.51 h66.67
  text "`" at -20.48,6314.73 h66.67
  text "4" at 503.38,6302.5 h60
  text "40.00mil (1.016mm)" at 1093.22,6302.5 h60
  text "PTH" at 2242.88,6302.5 h60
  text "Round" at 2748.76,6302.5 h60
  text "Top Layer - Bottom Layer" at 3482.56,6302.5 h60
  text "Pad" at 4982.11,6302.5 h60
  text "Rounded" at 5571.96,6302.5 h60
  text "c203h102" at 6317.76,6302.5 h60
  text "4" at 503.38,6152.5 h60
  text "57.09mil (1.450mm)" at 1093.22,6152.5 h60
  text "PTH" at 2242.88,6152.5 h60
  text "Round" at 2748.76,6152.5 h60
  text "Top Layer - Bottom Layer" at 3482.56,6152.5 h60
  text "Pad" at 4982.11,6152.5 h60
  text "(Mixed)" at 5571.96,6152.5 h60
  text "(Mixed)" at 6317.76,6152.5 h60
  text "6" at 503.38,6002.5 h60
  text "41.34mil (1.050mm)" at 1093.22,6002.5 h60
  text "PTH" at 2242.88,6002.5 h60
  text "Round" at 2748.76,6002.5 h60
  text "Top Layer - Bottom Layer" at 3482.56,6002.5 h60
  text "Pad" at 4982.11,6002.5 h60
  text "Rounded" at 5571.96,6002.5 h60
  text "c155h105" at 6317.76,6002.5 h60
  text "T" at -31.59,5992.51 h66.67
  text "6" at 503.38,5852.5 h60
  text "62.00mil (1.575mm)" at 1093.22,5852.5 h60
  text "PTH" at 2242.88,5852.5 h60
  text "Round" at 2748.76,5852.5 h60
  text "Top Layer - Bottom Layer" at 3482.56,5852.5 h60
  text "Pad" at 4982.11,5852.5 h60
  text "(Mixed)" at 5571.96,5852.5 h60
  text "(Mixed)" at 6317.76,5852.5 h60
  text "Y" at -31.59,5842.51 h66.67
  text "6" at 503.38,5702.5 h60
  text "78.74mil (2.000mm)" at 1093.22,5702.5 h60
  text "PTH" at 2242.88,5702.5 h60
  text "Round" at 2748.76,5702.5 h60
  text "Top Layer - Bottom Layer" at 3482.56,5702.5 h60
  text "Pad" at 4982.11,5702.5 h60
  text "(Mixed)" at 5571.96,5702.5 h60
  text "(Mixed)" at 6317.76,5702.5 h60
  text "M" at -31.59,5692.51 h66.67
  text "6" at 503.38,5552.5 h60
  text "125.00mil (3.175mm)" at 1093.22,5552.5 h60
  text "PTH" at 2242.88,5552.5 h60
  text "Round" at 2748.76,5552.5 h60
  text "Top Layer - Bottom Layer" at 3482.56,5552.5 h60
  text "Pad" at 4982.11,5552.5 h60
  text "Rounded" at 5571.96,5552.5 h60
  text "c533h318" at 6317.76,5552.5 h60
  text "Q" at -31.59,5542.51 h66.67
  text "6" at 503.38,5402.5 h60
  text "125.98mil (3.200mm)" at 1093.22,5402.5 h60
  text "PTH" at 2242.88,5402.5 h60
  text "Round" at 2748.76,5402.5 h60
  text "Top Layer - Bottom Layer" at 3482.56,5402.5 h60
  text "Pad" at 4982.11,5402.5 h60
  text "Rounded" at 5571.96,5402.5 h60
  text "c800h320" at 6317.76,5402.5 h60
  text "8" at 503.38,5252.5 h60
  text "35.43mil (0.900mm)" at 1093.22,5252.5 h60
  text "PTH" at 2242.88,5252.5 h60
  text "Round" at 2748.76,5252.5 h60
  text "Top Layer - Bottom Layer" at 3482.56,5252.5 h60
  text "Pad" at 4982.11,5252.5 h60
  text "Rounded" at 5571.96,5252.5 h60
  text "c140h90" at 6317.76,5252.5 h60
  text "U" at -31.59,5242.51 h66.67
  text "8" at 503.38,5102.5 h60
  text "59.06mil (1.500mm)" at 1093.22,5102.5 h60
  text "PTH" at 2242.88,5102.5 h60
  text "Round" at 2748.76,5102.5 h60
  text "Top Layer - Bottom Layer" at 3482.56,5102.5 h60
  text "Pad" at 4982.11,5102.5 h60
  text "(Mixed)" at 5571.96,5102.5 h60
  text "(Mixed)" at 6317.76,5102.5 h60
  text "N" at -31.59,5092.51 h66.67
  text "8" at 503.38,4952.5 h60
  text "60.00mil (1.524mm)" at 1093.22,4952.5 h60
  text "PTH" at 2242.88,4952.5 h60
  text "Round" at 2748.76,4952.5 h60
  text "Top Layer - Bottom Layer" at 3482.56,4952.5 h60
  text "Pad" at 4982.11,4952.5 h60
  text "(Mixed)" at 5571.96,4952.5 h60
  text "(Mixed)" at 6317.76,4952.5 h60
  text "9" at 503.38,4802.5 h60
  text "51.18mil (1.300mm)" at 1093.22,4802.5 h60
  text "PTH" at 2242.88,4802.5 h60
  text "Round" at 2748.76,4802.5 h60
  text "Top Layer - Bottom Layer" at 3482.56,4802.5 h60
  text "Pad" at 4982.11,4802.5 h60
  text "(Mixed)" at 5571.96,4802.5 h60
  text "(Mixed)" at 6317.76,4802.5 h60
  text "O" at -31.59,4792.51 h66.67
  text "a" at -31.59,4653.62 h66.67
  text "120" at 503.38,4652.5 h60
  text "10.00mil (0.254mm)" at 1093.22,4652.5 h60
  text "PTH" at 2242.88,4652.5 h60
  text "Round" at 2748.76,4652.5 h60
  text "Top Layer - Bottom Layer" at 3482.56,4652.5 h60
  text "Via" at 4982.11,4652.5 h60
  text "Rounded" at 5571.96,4652.5 h60
  text "(Mixed)" at 6317.76,4652.5 h60
  text "210 Total" at 503.38,4502.5 h60
  text ".Layer_Name" at 577,-858.49 h60

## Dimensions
0,0 to 6300,0 on M2 Board Dimensions
0,0 to 0,4500 on M2 Board Dimensions
0,-400 to 1000,-400 on M2 Board Dimensions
